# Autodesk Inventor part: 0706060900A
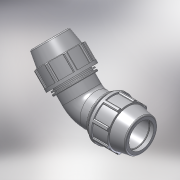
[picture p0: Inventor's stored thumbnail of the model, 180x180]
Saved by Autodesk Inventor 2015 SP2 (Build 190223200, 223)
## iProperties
Created: 2017-02
Part Number: 0706060900A
Material: PVC-Piping
Description: PLASSON 45° ELBOW 90-90
Document SubType Name: Modeling
Designer: KIM
Mass: 92.6774 g
Surface Area: 199.44 cm^2
Volume: 66.1981 cm^3
Density: 1.4 g/cm^3
Appearance: Smooth - White
Author: Кирилл
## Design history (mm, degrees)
derived "87060.ipt"
feature "Solid1::87060.ipt"
tag "TaggingFeature1"
body "Solid1"
other parameters: "d4" = 16.25, "d5" = 48.75, "d7" = 154, "d9" = 27.85714, "d11" = 6.5, "d13" = 120 deg, "d14" = 117, "d15" = 10 deg, "d16" = 133.98, "d18" = 4.5, "d19" = 35 deg, "d20" = 17.5 deg, "d21" = 143.22, "d23" = 0, "d25" = 360 deg, "d27" = 3.08, "d33" = 1.8, "d42" = 66.3, "d43" = 4.62, "d46" = 1.8, "d51" = 195, "d59" = 135 deg, "d63" = 165, "d64" = 81, "d67" = 115.5, "d68" = 11.7, "d70" = 45 deg, "d72" = 10.26667, "d73" = 0, "d75" = 135 deg, "d77" = 131.3004, "d78" = 3.9, "E_" = 154, "A_" = 195, "l_" = 165
